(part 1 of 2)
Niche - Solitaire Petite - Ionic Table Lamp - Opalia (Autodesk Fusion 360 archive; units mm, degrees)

design "Marble Base - Ionic Table Lamp - Ketra Ready - 120V - Opalia Collection" references "Dart", "Orb 8.5In - Solitaire Petite", "Dart Petite", "Arca Petite", "Facet Petite", "Arca Tall", "Chinois", "Marble Base - Ionic Table Lamp - Ketra Ready - 120V", "Trove - TL", "Ketra - A20 Tunable Lamp"
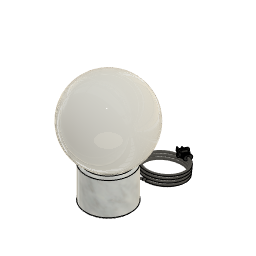
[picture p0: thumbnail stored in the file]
component_insert "Component Insert2"
component_insert "Component Insert3"
component_insert "Component Insert4"
component_insert "Component Insert5"
position "Position1"
component_insert "Component Insert6"
component_insert "Component Insert7"
component_insert "Component Insert8"
external_derived "ExternalDerived1" bodies "Orb-8.5"
derived_instance "DerivedInstance1"
position "Position2"
external_derived "ExternalDerived2" bodies "Dart Grand"
derived_instance "DerivedInstance2"
offset_faces "OffsetFaces1" distance -10.16
position "Position3"
external_derived "ExternalDerived3" bodies "Dart Petite"
derived_instance "DerivedInstance3"
offset_faces "OffsetFaces1" distance -10.16
position "Position4"
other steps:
derived_base_feature "Derived Base Feature1" bodies "Dart Grand"
derived_base_feature "Derived Base Feature1" bodies "Dart Petite"
derived_base_feature "Derived Base Feature1" bodies "Orb-8.5"
create_component "CreateComponent1"
create_component "CreateComponent2"
create_component "CreateComponent3"
named bodies: "Orb-8.5", "Dart Grand", "Dart Petite"

design "Dart Petite"
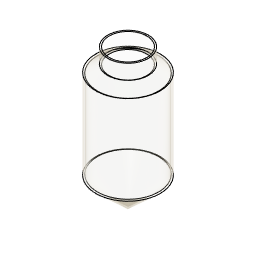
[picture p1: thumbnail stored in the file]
sketch "Sketch1" plane through (0, 0, 0) normal (0, 0, 1) x axis (1, 0, 0)
work_plane "WorkPlane1" AlongDistance 76.2
sketch "Sketch2" plane through (0, 0, 76.2) normal (0, 0, 1) x axis (1, 0, 0)
sketch "Sketch3" plane through (0, 0, 76.2) normal (0, 0, 1) x axis (1, 0, 0)
sketch "Sketch4" plane through (0, 0, 76.2) normal (0, 0, 1) x axis (1, 0, 0)
  circle C1 centre (0, 0) radius 82.55
  point P1 (0, 0)
  point P2 (0, 0)
  coincident P1 P2
  dimension "d2" diameter C1 = 165.1
loft "Loft1" sketch "Sketch4" bodies "Dart Petite"
extrude "Extrude1" add of existing geometry blind 228.6
work_plane "WorkPlane2" AlongDistance 19.05
sketch "Sketch5" plane through (0, 0, 323.85) normal (0, 0, 1) x axis (1, 0, 0)
  circle C1 centre (0, 0) radius 52.07
  point P1 (0, 0)
  point P2 (0, 0)
  coincident P1 P2
  dimension "d6" diameter C1 = 104.14
loft "Loft2" sketch "Sketch5"
extrude "Extrude2" add of existing geometry blind 38.1
shell "Shell3" innerThickness 3.81
component_from_bodies "Body->Comp"
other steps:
base_feature "Base Feature" bodies "Dart Petite"
create_component "CreateComponent1"
remove_body "RemoveBody1"
named bodies: "Dart Petite"

design "Marble Base - Ionic Table Lamp - Ketra Ready - 120V" references "Marble Base - Ionic Table Lamp - 120V"
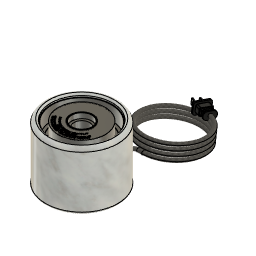
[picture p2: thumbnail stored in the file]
external_derived "ExternalDerived1" bodies "Coiled - SVT (Blk Fabric)", "Body1", "Marble Base", "Body2", "Silicone Gasket", "Plastic Insert"
derived_instance "DerivedInstance1"
derived_instance "DerivedInstance2"
derived_instance "DerivedInstance3"
derived_instance "DerivedInstance4"
derived_instance "DerivedInstance5"
derived_instance "DerivedInstance6"
derived_instance "DerivedInstance7"
derived_instance "DerivedInstance8"
derived_instance "DerivedInstance9"
derived_instance "DerivedInstance10"
derived_instance "DerivedInstance11"
derived_instance "DerivedInstance12"
offset_faces "OffsetFaces1" distance 3.81
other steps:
derived_base_feature "Derived Base Feature1" bodies "Rubber Grommet"
derived_base_feature "Derived Base Feature1" bodies "Neoprene Pad"
derived_base_feature "Derived Base Feature1" bodies "2-Pole Plug End"
derived_base_feature "Derived Base Feature1" bodies "Body1"
derived_base_feature "Derived Base Feature1" bodies "Body1", "Body2"
derived_base_feature "Derived Base Feature1" bodies "Body1"
derived_base_feature "Derived Base Feature1" bodies "Silicone Gasket"
derived_base_feature "Derived Base Feature1" bodies "Plastic Insert"
derived_base_feature "Derived Base Feature1" bodies "Body1"
derived_base_feature "Derived Base Feature1" bodies "Body1"
derived_base_feature "Derived Base Feature1" bodies "Coiled - SVT (Blk Fabric)"
derived_base_feature "Derived Base Feature1" bodies "Marble Base"
create_component "CreateComponent1"
create_component "CreateComponent2"
create_component "CreateComponent3"
create_component "CreateComponent4"
create_component "CreateComponent5"
create_component "CreateComponent6"
create_component "CreateComponent7"
create_component "CreateComponent8"
create_component "CreateComponent9"
create_component "CreateComponent10"
create_component "CreateComponent11"
create_component "CreateComponent12"
named bodies: "Coiled - SVT (Blk Fabric)", "Marble Base", "Body1", "Body2", "Plastic Insert", "Silicone Gasket", "Neoprene Pad", "2-Pole Plug End", "Rubber Grommet"

design "Arca Petite"
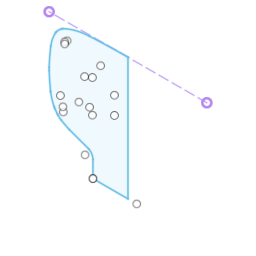
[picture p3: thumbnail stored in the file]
sketch "Sketch1" plane through (0, 0, 0) normal (0, 1, 0) x axis (1, 0, 0)
  line L1 (0, 101.6) -> (0, -101.6)
  line L2 (127, 0) -> (-127, 0)
  line L3 (63.5, 101.6) -> (-63.5, 101.6)
  perpendicular L1 L2
  parallel L2 L3
sketch "Sketch2" plane through (0, 0, 0) normal (0, 1, 0) x axis (1, 0, 0)
  line L1 (0, 101.6) -> (0, -101.6)
  line L2 (0, -76.2) -> (0, 101.6)
  line L3 (127, 0) -> (-127, 0)
  line L4 (114.3, 0) -> (-114.3, 0)
  line L5 (50.8, 101.6) -> (50.8, 63.5)
  line L6 (-50.8, 101.6) -> (50.8, 101.6)
  line L7 (-50.8, 63.5) -> (-50.8, 101.6)
  line L8 (63.5, 101.6) -> (-63.5, 101.6)
  line L9 (114.3, -76.2) -> (114.3, 63.5)
  line L10 (-114.3, -76.2) -> (114.3, -76.2)
  line L11 (-114.3, 63.5) -> (-114.3, -76.2)
  line L12 (-50.8, 63.5) -> (-114.3, 63.5)
  line L13 (114.3, 63.5) -> (50.8, 63.5)
  point P2 (0, 101.6)
  point P5 (0, 101.6)
  point P6 (0, -76.2)
  point P9 (-114.3, 0)
  point P10 (114.3, 0)
  point P11 (50.8, 101.6)
  point P19 (50.8, 63.5)
  coincident P2 P5
  coincident L1 P6
  coincident L3 P9
  coincident L3 P10
  vertical L5
  horizontal L6
  vertical L7
  coincident P11 L8
  horizontal L12
  vertical L9
  horizontal L10
  vertical L11
  coincident P19 L12
  collinear L12 L13
derived_base_feature "Derived Base Feature"
revolve "Revolve1" sketch "Sketch4" AlongAngle 360 bodies "Arca Petite"
shell "Shell1" innerThickness 3.81
component_from_bodies "Body->Comp"
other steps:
base_feature "Base Feature" bodies "Arca Petite"
create_component "CreateComponent1"
remove_body "RemoveBody1"
named bodies: "Arca Petite"

design "Neoprene Pad"
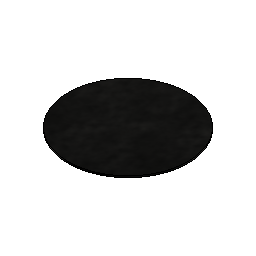
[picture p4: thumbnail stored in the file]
sketch "Sketch1" plane through (0, 0, 0) normal (0, 0, 1) x axis (1, 0, 0)
  circle C1 centre (0, 0) radius 57.15
  point P1 (0, 0)
  point P2 (0, 0)
  coincident P1 P2
extrude "Extrude1" new body sketch "Sketch1" along normal blind 1.5875 bodies "Neoprene Pad"
component_from_bodies "Body->Comp"
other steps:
base_feature "Base Feature" bodies "Neoprene Pad"
create_component "CreateComponent1"
remove_body "RemoveBody1"
named bodies: "Neoprene Pad"

design "T9 - Bulb"
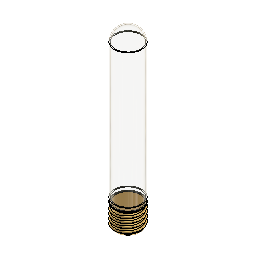
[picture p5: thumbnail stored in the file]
sketch "Sketch1" plane through (0, 0, 0) normal (0, 1, 0) x axis (1, 0, 0)
  line L1 (0, -166.37) -> (0, 0)
  line L2 (13.97, -13.97) -> (13.97, -152.4)
  line L3 (-13.97, -152.4) -> (-13.97, -13.97)
  line L4 (0, 0) -> (0, -166.37)
  line L5 (12.97, -13.97) -> (12.97, -152.4)
  line L6 (-12.97, -152.4) -> (-12.97, -13.97)
  line L7 (-12.3978, -10.16) -> (-13.4404, -10.16)
  line L8 (13.4404, -10.16) -> (12.3978, -10.16)
  arc A1 centre (0, -152.4) radius 13.97 clockwise from (13.97, -152.4) to (-13.97, -152.4)
  arc A2 centre (0, -152.4) radius 12.97 clockwise from (12.97, -152.4) to (-12.97, -152.4)
  arc A3 centre (0, -13.97) radius 13.97 clockwise from (13.4404, -10.16) to (13.97, -13.97)
  arc A4 centre (0, -13.97) radius 13.97 clockwise from (-13.97, -13.97) to (-13.4404, -10.16)
  arc A5 centre (0, -13.97) radius 12.97 clockwise from (12.3978, -10.16) to (12.97, -13.97)
  arc A6 centre (0, -13.97) radius 12.97 clockwise from (-12.97, -13.97) to (-12.3978, -10.16)
  point P1 (0, 0)
  point P2 (0, 0)
  point P3 (0, -166.37)
  point P10 (0, 0)
  point P17 (13.4404, -10.16)
  point P19 (12.3978, -10.16)
  point P4 (13.97, -152.4)
  point P5 (13.97, -13.97)
  coincident P1 P2
  vertical L1
  tangent L2 A3
  tangent L3 A3
  parallel L2 L3
  tangent L3 A1
  tangent L2 A1
  midpoint P3 A1
  coincident P1 P10
  perpendicular L1 L7
  coincident P17 L7
  concentric A3 A4
  coincident P10 A3
  concentric A1 A2
  tangent L5 A2
  tangent L5 A5
  tangent L6 A5
  tangent L6 A2
  coincident P19 L7
  concentric A5 A6
  collinear L7 L8
  dimension "d6" distance L2 L3 = 27.94
  dimension "d7" distance P4 P5 = 138.43
revolve "Revolve1" sketch "Sketch1" AlongAngle 360 bodies "T9"
derived_base_feature "Derived Base Feature" bodies "E26 Base"
align "Align1"
move "Move1"
component_from_bodies "Body->Comp1"
component_from_bodies "Body->Comp2"
copy_paste "CutPaste1"
copy_paste "CutPaste2"
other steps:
base_feature "Base Feature1" bodies "T9"
base_feature "Base Feature1" bodies "E26 Base"
create_component "CreateComponent1"
create_component "CreateComponent2"
remove_body "RemoveBody1"
create_component "CreateComponent3"
remove_body "RemoveBody2"
remove_instance "RemoveInstance1"
remove_instance "RemoveInstance2"
named bodies: "T9", "E26 Base"

design "Facet Petite"
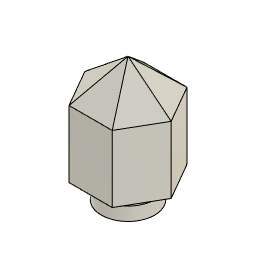
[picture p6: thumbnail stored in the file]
sketch "Sketch7" plane through (0, 0, 0) normal (1, 0, 0) x axis (0, 1, 0)
sketch "Sketch8" plane through (0, 0, 0) normal (0, 0, 1) x axis (1, 0, 0)
  circle C1 centre (0, 0) radius 50.8
  point P1 (0, 0)
  point P2 (0, 0)
  coincident P1 P2
  dimension "d17" diameter C1 = 101.6
extrude "Extrude5" new body sketch "Sketch8" along normal blind 25.4 and against normal blind 25.4
work_plane "WorkPlane1" AlongDistance 17.78
sketch "Sketch10" plane through (0, 0, 25.4) normal (0, 0, 1) x axis (-1, 0, 0)
  circle C1 centre (0, 0) radius 50.8
sketch "Sketch12" plane through (0, 0, 43.18) normal (0, 0, 1) x axis (1, 0, 0)
  line L1 (-82.1223, 0) -> (-41.0612, 71.12)
  line L2 (-41.0612, -71.12) -> (-82.1223, 0)
  line L3 (41.0612, -71.12) -> (-41.0612, -71.12)
  line L4 (82.1223, 0) -> (41.0612, -71.12)
  line L5 (41.0612, 71.12) -> (82.1223, 0)
  line L6 (-41.0612, 71.12) -> (41.0612, 71.12)
  point P1 (0, 0)
  point P8 (0, 0)
  coincident P1 P8
  dimension "d22" distance P8 L6 = 71.12
sketch "Sketch15" plane through (0, 0, 0) normal (0, 1, 0) x axis (1, 0, 0)
  line L1 (53.7365, -21.6801) -> (82.1223, -43.18)
  line L2 (-50.8, -25.4) -> (-82.1223, -43.18)
  point P2 (82.1223, -43.18)
  point P3 (82.1223, -43.18)
  point P5 (-82.1223, -43.18)
  point P7 (-82.1223, -43.18)
  point P6 (-50.8, -25.4)
  point P8 (-50.8, -25.4)
  coincident P2 P3
  coincident P5 P7
  coincident P6 P8
sketch "Sketch17" plane through (0, 0, 25.4) normal (0, 0, 1) x axis (-1, 0, 0)
  line L1 (51.3255, 0) -> (0, 0)
  line L2 (73.3235, 0) -> (0, 0)
  line L3 (-41.0612, -71.12) -> (-25.4, -43.9941)
  line L4 (-36.6617, -63.5) -> (-25.4, -43.9941)
  line L5 (78.4305, 0) -> (0, 0)
  line L6 (41.0612, -71.12) -> (25.4, -43.9941)
  line L7 (25.4, 43.9941) -> (41.0612, 71.12)
  line L8 (73.3235, 0) -> (0, 0)
  line L9 (-25.4, 43.9941) -> (-41.0612, 71.12)
  line L10 (0, 0) -> (0, 0)
  circle C1 centre (0, 0) radius 50.8
  point P1 (0, 0)
  point P4 (0, 0)
  point P2 (-41.0612, -71.12)
  point P6 (-41.0612, -71.12)
  point P3 (0, 0)
  point P7 (0, 0)
  point P9 (-25.4, -43.9941)
  point P12 (41.0612, -71.12)
  point P13 (41.0612, -71.12)
  point P15 (25.4, -43.9941)
  point P16 (41.0612, 71.12)
  point P17 (41.0612, 71.12)
  point P18 (25.4, 43.9941)
  point P19 (-41.0612, 71.12)
  point P20 (-41.0612, 71.12)
  point P21 (0, 0)
  point P23 (-25.4, 43.9941)
  point P25 (0, 0)
  point P24 (0, 0)
  point P26 (0, 0)
  horizontal L1
  coincident P1 P4
  coincident P2 P6
  horizontal L2
  coincident P3 P7
  coincident C1 P9
  coincident P12 P13
  horizontal L5
  coincident C1 P15
  coincident P16 P17
  coincident C1 P18
  coincident P19 P20
  horizontal L8
  coincident P1 P21
  coincident C1 P23
  coincident P1 P25
  coincident P24 P26
extrude "Extrude6" new body sketch "Sketch12" along normal blind 127
work_plane "WorkPlane2" AlongDistance 66.04
sketch "Sketch18" plane through (0, 0, 236.22) normal (0, 0, 1) x axis (1, 0, 0)
  line L1 (41.0612, -71.12) -> (0, 0)
  line L2 (82.1223, 0) -> (0, 0)
  line L3 (41.0612, 71.12) -> (0, 0)
  line L4 (-41.0612, 71.12) -> (0, 0)
  line L5 (-82.1223, 0) -> (0, 0)
  line L6 (-41.0612, -71.12) -> (0, 0)
  point P1 (0, 0)
  point P3 (0, 0)
  point P2 (41.0612, -71.12)
  point P4 (41.0612, -71.12)
  point P6 (0, 0)
  point P5 (82.1223, 0)
  point P7 (82.1223, 0)
  point P9 (0, 0)
  point P8 (41.0612, 71.12)
  point P10 (41.0612, 71.12)
  point P12 (0, 0)
  point P11 (-41.0612, 71.12)
  point P13 (-41.0612, 71.12)
  point P15 (0, 0)
  point P14 (-82.1223, 0)
  point P16 (-82.1223, 0)
  point P18 (0, 0)
  point P17 (-41.0612, -71.12)
  point P19 (-41.0612, -71.12)
  coincident P1 P3
  coincident P2 P4
  coincident P1 P6
  coincident P5 P7
  coincident P1 P9
  coincident P8 P10
  coincident P1 P12
  coincident P11 P13
  coincident P1 P15
  coincident P14 P16
  coincident P1 P18
  coincident P17 P19
loft "Loft1"
loft "Loft2" sketch "Sketch17"
component_from_bodies "Body->Comp"
extrude "Extrude1" cut of existing geometry blind -25.4
shell "Shell2" innerThickness 3.81
fillet "Fillet1" radius 7.62
fillet "Fillet2" radius 6.35
fillet "Fillet3" radius 6.35
fillet "Fillet4" radius 6.35
fillet "Fillet5" radius 6.35
fillet "Fillet6" radius 6.35
fillet "Fillet7" radius 3.81
fillet "Fillet8" radius 6.35
fillet "Fillet9" radius 6.35
fillet "Fillet10" radius 6.35
fillet "Fillet11" radius 6.35
fillet "Fillet12" radius 6.35
fillet "Fillet13" radius 2.286
shell "Shell1" innerThickness 2.54
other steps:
base_feature "Base Feature"
create_component "CreateComponent3"
remove_body "RemoveBody2"

design "Marble Base - Ionic Table Lamp - 120V" references "Dart", "Rubber Grommet", "Marble Base - Plastic Insert", "Chinois", "2-Pole Plug End", "Neoprene Pad", "Marble Base - Silicone Gasket", "Trove - TL", "Dart Petite", "Balon v2", "T9 - Bulb", "Orb 8.5In - Solitaire Petite", "T9-5In", "T8 LED 11", "Arca Tall", "Facet Petite"
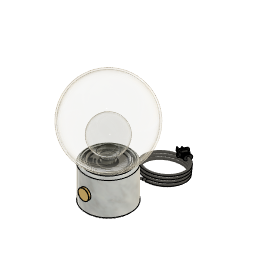
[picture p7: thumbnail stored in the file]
sketch "Sketch1" plane through (0, 0, 0) normal (0, 0, 1) x axis (1, 0, 0)
  circle C1 centre (0, 0) radius 63.5
  point P1 (0, 0)
  point P2 (0, 0)
  coincident P1 P2
extrude "Extrude1" new body sketch "Sketch1" along normal blind 101.6 bodies "Marble Base"
sketch "Sketch2" plane through (0, 0, 101.6) normal (0, 0, 1) x axis (-1, 0, 0)
  circle C1 centre (0, 0) radius 63.5
  circle C2 centre (0, 0) radius 53.975
  concentric C1 C2
  dimension "d3" diameter C2 = 107.95
extrude "Extrude2" cut sketch "Sketch2" profile of C2 against normal blind 34.925
sketch "Sketch3" plane through (0, 0, 66.675) normal (0, 0, 1) x axis (-1, 0, 0)
  circle C1 centre (0, 0) radius 53.975
  circle C2 centre (0, 0) radius 49.276
  point P1 (0, 0)
  point P3 (0, 0)
  coincident P1 P3
  dimension "d6" diameter C2 = 98.552
extrude "Extrude3" cut sketch "Sketch3" profile of C2 against normal blind 45.72
sketch "Sketch4" plane through (0, 0, 0) normal (0, 1, 0) x axis (1, 0, 0)
  circle C1 centre (0, -50.8) radius 3.81
  dimension "d9" diameter C1 = 7.62
extrude "Extrude4" cut sketch "Sketch4" against normal blind 127
sketch "Sketch5" plane through (0, 0, 0) normal (0, 1, 0) x axis (1, 0, 0)
  line L1 (0, -25.4) -> (0, 0)
  line L2 (0, -30.48) -> (0, -25.4)
  circle C1 centre (0, -30.48) radius 5.08
  point P1 (0, 0)
  point P2 (0, 0)
  point P4 (0, -30.48)
  point P5 (0, -30.48)
  coincident P1 P2
  vertical L1
  parallel L1 L2
  coincident P4 P5
  dimension "d12" diameter C1 = 10.16
extrude "Extrude5" cut sketch "Sketch5" profile of C1 along normal blind 114.3
fillet "Fillet1" radius 6.35 3.175 4.064
derived_base_feature "Derived Base Feature1" bodies "Rotary Switch"
derived_base_feature "Derived Base Feature1" bodies "Coiled - SVT (Blk Fabric)"
derived_base_feature "Derived Base Feature1" bodies "Glass Globe"
derived_base_feature "Derived Base Feature1" bodies "Metal Housing"
derived_base_feature "Derived Base Feature1" bodies "Metal Socket Cover"
derived_base_feature "Derived Base Feature1" bodies "Porcelain Socket"
derived_base_feature "Derived Base Feature1" bodies "Brass Dial - Dimmer Knob"
component_from_bodies "Body->Comp1"
offset_faces "OffsetFaces1" distance 12.7
offset_faces "OffsetFaces2" distance -12.7
derived_base_feature "Derived Base Feature1" bodies "Solitaire Petite"
move "Move1"
offset_faces "OffsetFaces1" distance 20.32
move "Move2"
extrude "Extrude6" add of existing geometry blind 25.4
offset_faces "OffsetFaces2" distance -3.81
fillet "Fillet2" radius 2.54
move "Move3"
derived_base_feature "Derived Base Feature2" bodies "Facet Petite"
move "Move4"
offset_faces "OffsetFaces1" distance 2.54
move "Move1"
derived_base_feature "Derived Base Feature1" bodies "Body1"
derived_base_feature "Derived Base Feature1" bodies "Body1"
derived_base_feature "Derived Base Feature1" bodies "Body1"
derived_base_feature "Derived Base Feature1" bodies "Body1"
derived_base_feature "Derived Base Feature1" bodies "Body1"
derived_base_feature "Derived Base Feature1" bodies "Body1", "Body2"
derived_base_feature "Derived Base Feature1" bodies "Body1"
position "Position1"
external_derived "ExternalDerived5" bodies "Plastic Insert"
derived_instance "DerivedInstance15"
offset_faces "OffsetFaces1" distance 3.81
offset_faces "OffsetFaces2" distance -1.0414
move "Move6"
external_derived "ExternalDerived6" sketch "Sketch3" bodies "Silicone Gasket"
derived_instance "DerivedInstance16"
offset_faces "OffsetFaces3" distance -10.795
move "Move1"
move_face "MoveFace1"
position "Position2"
position "Position3"
position "Position4"
position "Position5"
move "Move2"
position "Position6"
offset_faces "OffsetFaces2" distance -7.62
chamfer "Chamfer1" distance 0.381
remove_instance "RemoveInstance1"
remove_instance "RemoveInstance2"
remove_instance "RemoveInstance3"
remove_instance "RemoveInstance4"
move "Move1"
derived_base_feature "Derived Base Feature5" bodies "Oculo Petite"
align "Align1"
external_derived "ExternalDerived8"
derived_base_feature "Derived Base Feature7" bodies "Balon v2"
derived_base_feature "Derived Base Feature8" bodies "Balon v3"
align "Align3"
align "Align4"
external_derived "ExternalDerived10"
component_insert "Component Insert1"
position "Position7"
position "Position8"
derived_base_feature "Derived Base Feature11" bodies "Trove - TL"
move "Move10"
move "Move11"
remove_instance "RemoveInstance5"
split "Split1" bodies "Trove - TL (1)"
remove_body "RemoveBody2"
remove_body "RemoveBody3"
external_derived "ExternalDerived13" bodies "Trove - TL"
derived_instance "DerivedInstance20"
remove_body "RemoveBody4"
remove_body "RemoveBody5"
component_insert "Component Insert2"
component_insert "Component Insert3"
component_from_bodies "Body->Comp2"
remove_body "RemoveBody7"
move "Move12"
move "Move13"
sketch "Sketch6" plane through (0, 0, 97.917) normal (0, 0, 1) x axis (-1, 0, 0)
  circle C1 centre (0, 0) radius 41.275
  circle C2 centre (0, 0) radius 19.685
  arc A1 centre (0, 0) radius 29.3982 clockwise from (-27.6283, 10.0466) to (27.6283, 10.0466)
  arc A2 centre (0, 0) radius 26.2232 clockwise from (-24.6444, 8.9616) to (24.6444, 8.9616)
  arc A3 centre (0, 0) radius 32.5732 clockwise from (-30.6121, 11.1317) to (30.6121, 11.1317)
  arc A4 centre (0, 0) radius 35.7482 clockwise from (-33.596, 12.2167) to (33.596, 12.2167)
  point P1 (0, 0)
  point P3 (0, 0)
  coincident P1 P3
  dimension "d37" = -3.175
  dimension "d38" = 3.175
  dimension "d39" = 6.35
  dimension "d40" Text1-Height = 2.54
  dimension "d41" Text2-Height = 2.54
  dimension "d42" Text3-Height = 2.54
  dimension "d43" Text4-Height = 2.54
extrude "Extrude1" cut sketch "Sketch6" against normal blind 0.254
external_derived "ExternalDerived14" bodies "Rubber Grommet"
derived_instance "DerivedInstance19"
external_derived "ExternalDerived15" bodies "2-Pole Plug End"
derived_instance "DerivedInstance18"
external_derived "ExternalDerived16" bodies "Neoprene Pad"
derived_instance "DerivedInstance17"
position "Position9"
position "Position10"
position "Position11"
position "Position12"
external_derived "ExternalDerived17" bodies "Chinois"
derived_instance "DerivedInstance21"
position "Position13"
move "Move3"
remove_body "RemoveBody8"
component_insert "Component Insert4"
offset_faces "OffsetFaces3" distance 50.8
component_insert "Component Insert5"
position "Position14"
external_derived "ExternalDerived18" bodies "Dart Grand"
derived_instance "DerivedInstance22"
offset_faces "OffsetFaces1" distance -10.16
position "Position15"
external_derived "ExternalDerived19" bodies "Dart Petite"
derived_instance "DerivedInstance23"
offset_faces "OffsetFaces1" distance -10.16
position "Position16"
component_insert "Component Insert6"
position "Position17"
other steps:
derived_base_feature "Derived Base Feature1" bodies "Trove - TL"
derived_base_feature "Derived Base Feature1" bodies "Chinois"
derived_base_feature "Derived Base Feature1" bodies "Dart Grand"
derived_base_feature "Derived Base Feature1" bodies "Dart Petite"
derived_base_feature "Derived Base Feature1" bodies "Rubber Grommet"
derived_base_feature "Derived Base Feature1" bodies "Neoprene Pad"
derived_base_feature "Derived Base Feature1" bodies "2-Pole Plug End"
move "Move1"
derived_base_feature "Derived Base Feature1" bodies "Plastic Insert"
derived_base_feature "Derived Base Feature1" bodies "Silicone Gasket"
base_feature "Base Feature1" bodies "Oculo Petite", "Arca Petite"
base_feature "Base Feature1" bodies "Marble Base"
move "Move8"
derived_base_feature "Derived Base Feature"
create_component "CreateComponent1"
create_component "CreateComponent2"
create_component "CreateComponent3"
create_component "CreateComponent4"
create_component "CreateComponent5"
create_component "CreateComponent6"
create_component "CreateComponent7"
create_component "CreateComponent8"
remove_body "RemoveBody1"
create_component "CreateComponent9"
create_component "CreateComponent10"
create_component "CreateComponent11"
create_component "CreateComponent12"
create_component "CreateComponent13"
create_component "CreateComponent14"
create_component "CreateComponent15"
create_component "CreateComponent16"
create_component "CreateComponent17"
create_component "CreateComponent18"
remove_body "RemoveBody6"
create_component "CreateComponent19"
create_component "CreateComponent20"
create_component "CreateComponent21"
create_component "CreateComponent22"
create_component "CreateComponent23"
create_component "CreateComponent24"
create_component "CreateComponent25"
named bodies: "Marble Base", "Rotary Switch", "Coiled - SVT (Blk Fabric)", "Glass Globe", "Metal Housing", "Metal Socket Cover", "Porcelain Socket", "Brass Dial - Dimmer Knob", "Solitaire Petite", "Facet Petite", "Body1", "Body2", "Plastic Insert", "Silicone Gasket", "Oculo Petite", "Balon v2", "Balon v3", "Trove - TL", "Trove - TL (1)", "Arca Petite", "Neoprene Pad", "2-Pole Plug End", "Rubber Grommet", "Chinois", "Dart Grand", "Dart Petite"

design "Marble Base - Silicone Gasket"
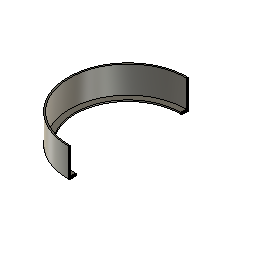
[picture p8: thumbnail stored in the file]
sketch "Sketch1" plane through (0, 0, 0) normal (0, 0, 1) x axis (1, 0, 0)
  circle C1 centre (0, 0) radius 53.34
  point P1 (0, 0)
  point P2 (0, 0)
  coincident P1 P2
extrude "Extrude1" new body sketch "Sketch1" along normal blind 25.4 bodies "Silicone Gasket"
shell "Shell1" innerThickness 1.27
sketch "Sketch2" plane through (0, 0, 1.27) normal (0, 0, 1) x axis (-1, 0, 0)
  circle C1 centre (0, 0) radius 52.07
  circle C2 centre (0, 0) radius 46.99
  concentric C1 C2
extrude "Extrude2" cut sketch "Sketch2" profile of C2 against normal blind 12.7
component_from_bodies "Body->Comp"
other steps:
base_feature "Base Feature" bodies "Silicone Gasket"
create_component "CreateComponent1"
remove_body "RemoveBody1"
named bodies: "Silicone Gasket"

design "Balon v2"
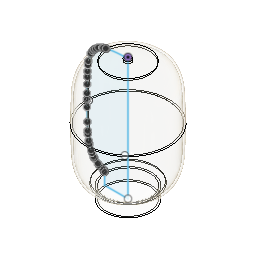
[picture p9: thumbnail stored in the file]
derived_base_feature "Derived Base Feature" bodies "Balon"
work_plane "WorkPlane1" AlongDistance 0
sketch "Sketch1" plane through (0, 0, 0) normal (0, 1, 0) x axis (1, 0, 0)
  line L1 (0, 317.5) -> (0, 2.9083)
  curve K1 (-82.9821, 124.2212) -> (-50.8, 237.8015)
  curve K2 (-51.0925, 237.681) -> (-50.8, 237.8015)
  curve K3 (-51.3855, 237.5558) -> (-51.0925, 237.681)
  curve K4 (-54.7608, 236.0513) -> (-51.3855, 237.5558)
  curve K5 (-57.9615, 234.05) -> (-54.7608, 236.0513)
  curve K6 (-67.2727, 226.749) -> (-57.9615, 234.05)
  curve K7 (-69.0552, 224.2615) -> (-67.2727, 226.749)
  curve K8 (-72.1872, 218.7832) -> (-69.0552, 224.2615)
  curve K9 (-74.1213, 215.1556) -> (-72.1872, 218.7832)
  curve K10 (-78.3031, 204.3965) -> (-74.1213, 215.1556)
  curve K11 (-79.7275, 197.3397) -> (-78.3031, 204.3965)
  curve K12 (-81.3333, 185.4664) -> (-79.7275, 197.3397)
  curve K13 (-81.6254, 178.4008) -> (-81.3333, 185.4664)
  curve K14 (-82.49, 152.2133) -> (-81.6254, 178.4008)
  curve K15 (-82.9821, 136.067) -> (-82.49, 152.2133)
  curve K16 (-82.9821, 124.2212) -> (-82.9821, 136.067)
  curve K17 (50.8, 237.7999) -> (82.9821, 124.2212)
  curve K18 (82.9821, 140.3031) -> (82.9821, 124.2212)
  curve K19 (81.9353, 169.4257) -> (82.9821, 140.3031)
  curve K20 (81.3621, 183.6489) -> (81.9353, 169.4257)
  curve K21 (80.9478, 189.8724) -> (81.3621, 183.6489)
  curve K22 (77.8147, 206.9858) -> (80.9478, 189.8724)
  curve K23 (74.9652, 213.2153) -> (77.8147, 206.9858)
  curve K24 (69.4688, 224.1531) -> (74.9652, 213.2153)
  curve K25 (67.2512, 226.458) -> (69.4688, 224.1531)
  curve K26 (61.5696, 231.3138) -> (67.2512, 226.458)
  curve K27 (57.377, 234.6711) -> (61.5696, 231.3138)
  curve K28 (52.0556, 237.2628) -> (57.377, 234.6711)
  curve K29 (51.4313, 237.5413) -> (52.0556, 237.2628)
  curve K30 (50.8, 237.7999) -> (51.4313, 237.5413)
  line L2 (-50.8, 317.5) -> (-50.8, 237.8015)
  line L3 (50.8, 317.5) -> (50.8, 237.7999)
  line L4 (-19.0713, 6.7501) -> (-19.0713, 6.7501)
  curve K31 (82.9821, 124.1958) -> (40.1509, 7.3012)
  curve K32 (41.8198, 7.6176) -> (40.1509, 7.3012)
  curve K33 (43.2113, 8.0663) -> (41.8198, 7.6176)
  curve K34 (47.0139, 9.2854) -> (43.2113, 8.0663)
  curve K35 (47.3314, 9.3805) -> (47.0139, 9.2854)
  curve K36 (50.1192, 10.3272) -> (47.3314, 9.3805)
  curve K37 (51.833, 11.0085) -> (50.1192, 10.3272)
  curve K38 (57.8313, 14.1895) -> (51.833, 11.0085)
  curve K39 (61.4491, 17.0488) -> (57.8313, 14.1895)
  curve K40 (66.8203, 21.5867) -> (61.4491, 17.0488)
  curve K41 (68.5372, 23.5528) -> (66.8203, 21.5867)
  curve K42 (71.2201, 27.8971) -> (68.5372, 23.5528)
  curve K43 (74.7424, 33.8984) -> (71.2201, 27.8971)
  curve K44 (78.2342, 44.8406) -> (74.7424, 33.8984)
  curve K45 (79.6792, 50.3463) -> (78.2342, 44.8406)
  curve K46 (81.3558, 63.5576) -> (79.6792, 50.3463)
  curve K47 (81.6386, 70.4415) -> (81.3558, 63.5576)
  curve K48 (82.4897, 96.2198) -> (81.6386, 70.4415)
  curve K49 (82.9814, 112.3523) -> (82.4897, 96.2198)
  curve K50 (82.9821, 124.1958) -> (82.9814, 112.3523)
  curve K51 (-40.1501, 7.301) -> (-82.9821, 124.1958)
  curve K52 (-82.9813, 110.5256) -> (-82.9821, 124.1958)
  curve K53 (-82.2545, 88.8594) -> (-82.9813, 110.5256)
  curve K54 (-81.6277, 70.519) -> (-82.2545, 88.8594)
  curve K55 (-81.3572, 64.3441) -> (-81.6277, 70.519)
  curve K56 (-79.4149, 46.8924) -> (-81.3572, 64.3441)
  curve K57 (-76.5204, 38.9768) -> (-79.4149, 46.8924)
  curve K58 (-73.5142, 32.2947) -> (-76.5204, 38.9768)
  curve K59 (-72.5556, 30.3818) -> (-73.5142, 32.2947)
  curve K60 (-69.7914, 25.3691) -> (-72.5556, 30.3818)
  curve K61 (-68.3824, 23.4028) -> (-69.7914, 25.3691)
  curve K62 (-64.5419, 19.5456) -> (-68.3824, 23.4028)
  curve K63 (-62.3002, 17.7646) -> (-64.5419, 19.5456)
  curve K64 (-53.6583, 11.1976) -> (-62.3002, 17.7646)
  curve K65 (-49.6968, 10.1396) -> (-53.6583, 11.1976)
  curve K66 (-43.4141, 8.1331) -> (-49.6968, 10.1396)
  curve K67 (-41.9704, 7.6516) -> (-43.4141, 8.1331)
  curve K68 (-40.1963, 7.3098) -> (-41.9704, 7.6516)
  curve K69 (-40.1732, 7.3054) -> (-40.1963, 7.3098)
  curve K70 (-40.1501, 7.301) -> (-40.1732, 7.3054)
  line L5 (-82.9821, 124.1958) -> (-82.9821, 124.2212)
  line L6 (82.9821, 124.2212) -> (82.9821, 124.1958)
  line L7 (0, 317.5) -> (-50.8, 317.5)
  line L8 (7.2015, 3.048) -> (0, 3.048)
  line L9 (0, 3.048) -> (-7.2015, 3.048)
  arc A1 centre (0, 188.595) radius 185.6867 clockwise from (-7.2015, 3.048) to (-40.1502, 7.301)
  arc A2 centre (0, 188.595) radius 185.6867 clockwise from (40.151, 7.3012) to (7.2015, 3.048)
  point P38 (-40.1502, 7.301)
  point P43 (40.1509, 7.3012)
  point P62 (-40.1501, 7.301)
  point P81 (40.151, 7.3012)
  point P84 (0, 3.048)
  vertical L1
  horizontal L4
  coincident P38 K51
  symmetric L1 A1 A2
  coincident A2 P43
  coincident A1 P62
  coincident K31 P81
  perpendicular L2 L7
  horizontal L8
  coincident L1 P84
  horizontal L9
revolve "Revolve1" sketch "Sketch1" AlongAngle 360
shell "Shell1" innerThickness 3.81
fillet "Fillet1" radius 6.35
offset_faces "OffsetFaces1" distance -50.8
move "Move1"
move "Move2"
component_from_bodies "Body->Comp1"
component_from_bodies "Body->Comp2"
sketch "Sketch2" plane through (0, 0, 0) normal (0, 1, 0) x axis (1, 0, 0)
  line L1 (-85.5221, 124.2212) -> (-85.5221, 124.1961)
  curve K1 (-58.9057, 236.4383) -> (-50.8, 241.7989)
  curve K2 (-50.8, 241.554) -> (-50.8, 241.7989)
  curve K3 (-50.904, 240.933) -> (-50.8, 241.554)
  curve K4 (-51.2936, 240.2837) -> (-50.904, 240.933)
  curve K5 (-51.734, 239.7561) -> (-51.2936, 240.2837)
  curve K6 (-53.328, 238.5038) -> (-51.734, 239.7561)
  curve K7 (-54.0892, 238.1997) -> (-53.328, 238.5038)
  curve K8 (-58.9057, 236.4383) -> (-54.0892, 238.1997)
  curve K9 (-89.3309, 124.2212) -> (-58.9057, 236.4383)
  curve K10 (-62.6336, 234.9735) -> (-58.9057, 236.4383)
  curve K11 (-65.581, 233.1032) -> (-62.6336, 234.9735)
  curve K12 (-73.0224, 227.0019) -> (-65.581, 233.1032)
  curve K13 (-74.8981, 224.836) -> (-73.0224, 227.0019)
  curve K14 (-78.1104, 219.6097) -> (-74.8981, 224.836)
  curve K15 (-80.2663, 215.561) -> (-78.1104, 219.6097)
  curve K16 (-84.0943, 205.8277) -> (-80.2663, 215.561)
  curve K17 (-85.4655, 200.1154) -> (-84.0943, 205.8277)
  curve K18 (-87.4092, 188.5789) -> (-85.4655, 200.1154)
  curve K19 (-87.7349, 182.3889) -> (-87.4092, 188.5789)
  curve K20 (-88.4233, 165.9645) -> (-87.7349, 182.3889)
  curve K21 (-89.328, 138.6964) -> (-88.4233, 165.9645)
  curve K22 (-89.3309, 124.2212) -> (-89.328, 138.6964)
  line L2 (-89.3309, 124.1958) -> (-89.3309, 124.2212)
  curve K23 (-46.5001, 7.301) -> (-89.3309, 124.1958)
  curve K24 (-89.3314, 112.4293) -> (-89.3309, 124.1958)
  curve K25 (-88.8181, 95.3068) -> (-89.3314, 112.4293)
  curve K26 (-88.346, 81.2892) -> (-88.8181, 95.3068)
  curve K27 (-88.0298, 70.4902) -> (-88.346, 81.2892)
  curve K28 (-87.1514, 58.328) -> (-88.0298, 70.4902)
  curve K29 (-86.3326, 50.6119) -> (-87.1514, 58.328)
  curve K30 (-81.0932, 33.6688) -> (-86.3326, 50.6119)
  curve K31 (-77.3163, 27.4309) -> (-81.0932, 33.6688)
  curve K32 (-74.8955, 23.6666) -> (-77.3163, 27.4309)
  curve K33 (-73.5108, 22.0741) -> (-74.8955, 23.6666)
  curve K34 (-70.2346, 19.0457) -> (-73.5108, 22.0741)
  curve K35 (-64.8094, 14.3548) -> (-70.2346, 19.0457)
  curve K36 (-56.6696, 10.3041) -> (-64.8094, 14.3548)
  curve K37 (-54.0053, 9.483) -> (-56.6696, 10.3041)
  curve K38 (-49.1487, 7.9411) -> (-54.0053, 9.483)
  curve K39 (-48.3482, 7.6526) -> (-49.1487, 7.9411)
  curve K40 (-46.5001, 7.301) -> (-48.3482, 7.6526)
  line L3 (0, 266.7) -> (0, 0)
  line L4 (0, 3.048) -> (-7.7894, 3.048)
  line L5 (-50.8, 266.7) -> (-50.8, 241.7989)
  line L6 (0, 266.7) -> (-50.8, 266.7)
  arc A1 centre (-6.9779, 188.7329) radius 185.6867 clockwise from (-7.7894, 3.048) to (-46.5001, 7.301)
  point P1 (0, 0)
  point P44 (0, 0)
  point P46 (0, 3.048)
  point P5 (-50.8, 241.554)
  point P49 (0, 266.7)
  coincident P1 P44
  coincident L3 P46
  coincident P5 L5
  coincident L3 P49
revolve "Revolve2" sketch "Sketch2" AlongAngle 360 bodies "Balon v3"
shell "Shell2" innerThickness 3.81
component_from_bodies "Body->Comp3"
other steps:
base_feature "Base Feature1" bodies "Balon"
base_feature "Base Feature1" bodies "Balon v3"
base_feature "Base Feature1" bodies "Balon v2"
create_component "CreateComponent1"
remove_body "RemoveBody1"
create_component "CreateComponent2"
remove_body "RemoveBody2"
create_component "CreateComponent3"
remove_body "RemoveBody3"
named bodies: "Balon", "Balon v2", "Balon v3"

design "Arca Tall"
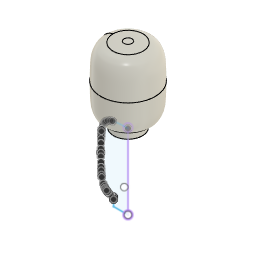
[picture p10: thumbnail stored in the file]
derived_base_feature "Derived Base Feature" bodies "Balon"
work_plane "WorkPlane1" AlongDistance 0
sketch "Sketch1" plane through (0, 0, 0) normal (0, 1, 0) x axis (1, 0, 0)
  line L1 (0, 317.5) -> (0, 2.9083)
  curve K1 (-82.9821, 124.2212) -> (-50.8, 237.8015)
  curve K2 (-51.0925, 237.681) -> (-50.8, 237.8015)
  curve K3 (-51.3855, 237.5558) -> (-51.0925, 237.681)
  curve K4 (-54.7608, 236.0513) -> (-51.3855, 237.5558)
  curve K5 (-57.9615, 234.05) -> (-54.7608, 236.0513)
  curve K6 (-67.2727, 226.749) -> (-57.9615, 234.05)
  curve K7 (-69.0552, 224.2615) -> (-67.2727, 226.749)
  curve K8 (-72.1872, 218.7832) -> (-69.0552, 224.2615)
  curve K9 (-74.1213, 215.1556) -> (-72.1872, 218.7832)
  curve K10 (-78.3031, 204.3965) -> (-74.1213, 215.1556)
  curve K11 (-79.7275, 197.3397) -> (-78.3031, 204.3965)
  curve K12 (-81.3333, 185.4664) -> (-79.7275, 197.3397)
  curve K13 (-81.6254, 178.4008) -> (-81.3333, 185.4664)
  curve K14 (-82.49, 152.2133) -> (-81.6254, 178.4008)
  curve K15 (-82.9821, 136.067) -> (-82.49, 152.2133)
  curve K16 (-82.9821, 124.2212) -> (-82.9821, 136.067)
  curve K17 (50.8, 237.7999) -> (82.9821, 124.2212)
  curve K18 (82.9821, 140.3031) -> (82.9821, 124.2212)
  curve K19 (81.9353, 169.4257) -> (82.9821, 140.3031)
  curve K20 (81.3621, 183.6489) -> (81.9353, 169.4257)
  curve K21 (80.9478, 189.8724) -> (81.3621, 183.6489)
  curve K22 (77.8147, 206.9858) -> (80.9478, 189.8724)
  curve K23 (74.9652, 213.2153) -> (77.8147, 206.9858)
  curve K24 (69.4688, 224.1531) -> (74.9652, 213.2153)
  curve K25 (67.2512, 226.458) -> (69.4688, 224.1531)
  curve K26 (61.5696, 231.3138) -> (67.2512, 226.458)
  curve K27 (57.377, 234.6711) -> (61.5696, 231.3138)
  curve K28 (52.0556, 237.2628) -> (57.377, 234.6711)
  curve K29 (51.4313, 237.5413) -> (52.0556, 237.2628)
  curve K30 (50.8, 237.7999) -> (51.4313, 237.5413)
  line L2 (-50.8, 317.5) -> (-50.8, 237.8015)
  line L3 (50.8, 317.5) -> (50.8, 237.7999)
  line L4 (-19.0713, 6.7501) -> (-19.0713, 6.7501)
  curve K31 (82.9821, 124.1958) -> (40.1509, 7.3012)
  curve K32 (41.8198, 7.6176) -> (40.1509, 7.3012)
  curve K33 (43.2113, 8.0663) -> (41.8198, 7.6176)
  curve K34 (47.0139, 9.2854) -> (43.2113, 8.0663)
  curve K35 (47.3314, 9.3805) -> (47.0139, 9.2854)
  curve K36 (50.1192, 10.3272) -> (47.3314, 9.3805)
  curve K37 (51.833, 11.0085) -> (50.1192, 10.3272)
  curve K38 (57.8313, 14.1895) -> (51.833, 11.0085)
  curve K39 (61.4491, 17.0488) -> (57.8313, 14.1895)
  curve K40 (66.8203, 21.5867) -> (61.4491, 17.0488)
  curve K41 (68.5372, 23.5528) -> (66.8203, 21.5867)
  curve K42 (71.2201, 27.8971) -> (68.5372, 23.5528)
  curve K43 (74.7424, 33.8984) -> (71.2201, 27.8971)
  curve K44 (78.2342, 44.8406) -> (74.7424, 33.8984)
  curve K45 (79.6792, 50.3463) -> (78.2342, 44.8406)
  curve K46 (81.3558, 63.5576) -> (79.6792, 50.3463)
  curve K47 (81.6386, 70.4415) -> (81.3558, 63.5576)
  curve K48 (82.4897, 96.2198) -> (81.6386, 70.4415)
  curve K49 (82.9814, 112.3523) -> (82.4897, 96.2198)
  curve K50 (82.9821, 124.1958) -> (82.9814, 112.3523)
  curve K51 (-40.1501, 7.301) -> (-82.9821, 124.1958)
  curve K52 (-82.9813, 110.5256) -> (-82.9821, 124.1958)
  curve K53 (-82.2545, 88.8594) -> (-82.9813, 110.5256)
  curve K54 (-81.6277, 70.519) -> (-82.2545, 88.8594)
  curve K55 (-81.3572, 64.3441) -> (-81.6277, 70.519)
  curve K56 (-79.4149, 46.8924) -> (-81.3572, 64.3441)
  curve K57 (-76.5204, 38.9768) -> (-79.4149, 46.8924)
  curve K58 (-73.5142, 32.2947) -> (-76.5204, 38.9768)
  curve K59 (-72.5556, 30.3818) -> (-73.5142, 32.2947)
  curve K60 (-69.7914, 25.3691) -> (-72.5556, 30.3818)
  curve K61 (-68.3824, 23.4028) -> (-69.7914, 25.3691)
  curve K62 (-64.5419, 19.5456) -> (-68.3824, 23.4028)
  curve K63 (-62.3002, 17.7646) -> (-64.5419, 19.5456)
  curve K64 (-53.6583, 11.1976) -> (-62.3002, 17.7646)
  curve K65 (-49.6968, 10.1396) -> (-53.6583, 11.1976)
  curve K66 (-43.4141, 8.1331) -> (-49.6968, 10.1396)
  curve K67 (-41.9704, 7.6516) -> (-43.4141, 8.1331)
  curve K68 (-40.1963, 7.3098) -> (-41.9704, 7.6516)
  curve K69 (-40.1732, 7.3054) -> (-40.1963, 7.3098)
  curve K70 (-40.1501, 7.301) -> (-40.1732, 7.3054)
  line L5 (-82.9821, 124.1958) -> (-82.9821, 124.2212)
  line L6 (82.9821, 124.2212) -> (82.9821, 124.1958)
  line L7 (0, 317.5) -> (-50.8, 317.5)
  line L8 (7.2015, 3.048) -> (0, 3.048)
  line L9 (0, 3.048) -> (-7.2015, 3.048)
  arc A1 centre (0, 188.595) radius 185.6867 clockwise from (-7.2015, 3.048) to (-40.1502, 7.301)
  arc A2 centre (0, 188.595) radius 185.6867 clockwise from (40.151, 7.3012) to (7.2015, 3.048)
  point P38 (-40.1502, 7.301)
  point P43 (40.1509, 7.3012)
  point P62 (-40.1501, 7.301)
  point P81 (40.151, 7.3012)
  point P84 (0, 3.048)
  vertical L1
  horizontal L4
  coincident P38 K51
  symmetric L1 A1 A2
  coincident A2 P43
  coincident A1 P62
  coincident K31 P81
  perpendicular L2 L7
  horizontal L8
  coincident L1 P84
  horizontal L9
revolve "Revolve1" sketch "Sketch1" AlongAngle 360
shell "Shell1" innerThickness 3.81
fillet "Fillet1" radius 6.35 bodies "Balon v3"
offset_faces "OffsetFaces1" distance -50.8
move "Move1"
move "Move2"
component_from_bodies "Body->Comp1"
component_from_bodies "Body->Comp2"
sketch "Sketch2" plane through (0, 0, 0) normal (0, 1, 0) x axis (1, 0, 0)
  line L1 (-85.5221, 124.2212) -> (-85.5221, 124.1961)
  curve K1 (-58.9057, 236.4383) -> (-50.8, 241.7989)
  curve K2 (-50.8, 241.554) -> (-50.8, 241.7989)
  curve K3 (-50.904, 240.933) -> (-50.8, 241.554)
  curve K4 (-51.2936, 240.2837) -> (-50.904, 240.933)
  curve K5 (-51.734, 239.7561) -> (-51.2936, 240.2837)
  curve K6 (-53.328, 238.5038) -> (-51.734, 239.7561)
  curve K7 (-54.0892, 238.1997) -> (-53.328, 238.5038)
  curve K8 (-58.9057, 236.4383) -> (-54.0892, 238.1997)
  curve K9 (-89.3309, 124.2212) -> (-58.9057, 236.4383)
  curve K10 (-62.6336, 234.9735) -> (-58.9057, 236.4383)
  curve K11 (-65.581, 233.1032) -> (-62.6336, 234.9735)
  curve K12 (-73.0224, 227.0019) -> (-65.581, 233.1032)
  curve K13 (-74.8981, 224.836) -> (-73.0224, 227.0019)
  curve K14 (-78.1104, 219.6097) -> (-74.8981, 224.836)
  curve K15 (-80.2663, 215.561) -> (-78.1104, 219.6097)
  curve K16 (-84.0943, 205.8277) -> (-80.2663, 215.561)
  curve K17 (-85.4655, 200.1154) -> (-84.0943, 205.8277)
  curve K18 (-87.4092, 188.5789) -> (-85.4655, 200.1154)
  curve K19 (-87.7349, 182.3889) -> (-87.4092, 188.5789)
  curve K20 (-88.4233, 165.9645) -> (-87.7349, 182.3889)
  curve K21 (-89.328, 138.6964) -> (-88.4233, 165.9645)
  curve K22 (-89.3309, 124.2212) -> (-89.328, 138.6964)
  line L2 (-89.3309, 124.1958) -> (-89.3309, 124.2212)
  curve K23 (-46.5001, 7.301) -> (-89.3309, 124.1958)
  curve K24 (-89.3314, 112.4293) -> (-89.3309, 124.1958)
  curve K25 (-88.8181, 95.3068) -> (-89.3314, 112.4293)
  curve K26 (-88.346, 81.2892) -> (-88.8181, 95.3068)
  curve K27 (-88.0298, 70.4902) -> (-88.346, 81.2892)
  curve K28 (-87.1514, 58.328) -> (-88.0298, 70.4902)
  curve K29 (-86.3326, 50.6119) -> (-87.1514, 58.328)
  curve K30 (-81.0932, 33.6688) -> (-86.3326, 50.6119)
  curve K31 (-77.3163, 27.4309) -> (-81.0932, 33.6688)
  curve K32 (-74.8955, 23.6666) -> (-77.3163, 27.4309)
  curve K33 (-73.5108, 22.0741) -> (-74.8955, 23.6666)
  curve K34 (-70.2346, 19.0457) -> (-73.5108, 22.0741)
  curve K35 (-64.8094, 14.3548) -> (-70.2346, 19.0457)
  curve K36 (-56.6696, 10.3041) -> (-64.8094, 14.3548)
  curve K37 (-54.0053, 9.483) -> (-56.6696, 10.3041)
  curve K38 (-49.1487, 7.9411) -> (-54.0053, 9.483)
  curve K39 (-48.3482, 7.6526) -> (-49.1487, 7.9411)
  curve K40 (-46.5001, 7.301) -> (-48.3482, 7.6526)
  line L3 (0, 266.7) -> (0, 0)
  line L4 (0, 3.048) -> (-7.7894, 3.048)
  line L5 (-50.8, 266.7) -> (-50.8, 241.7989)
  line L6 (0, 266.7) -> (-50.8, 266.7)
  arc A1 centre (-6.9779, 188.7329) radius 185.6867 clockwise from (-7.7894, 3.048) to (-46.5001, 7.301)
  point P1 (0, 0)
  point P44 (0, 0)
  point P46 (0, 3.048)
  point P5 (-50.8, 241.554)
  point P49 (0, 266.7)
  coincident P1 P44
  coincident L3 P46
  coincident P5 L5
  coincident L3 P49
revolve "Revolve2" sketch "Sketch2" AlongAngle 360 bodies "Balon v3"
shell "Shell2" innerThickness 3.81
component_from_bodies "Body->Comp3"
remove_instance "RemoveInstance1"
remove_instance "RemoveInstance2"
sketch "Sketch1" plane through (0, 0, 0) normal (0, 1, 0) x axis (1, 0, 0)
  line L1 (-6.35, 3.048) -> (-14.1394, 3.048)
  curve K1 (-52.8501, 7.301) -> (-95.6809, 124.1958)
  curve K2 (-95.6814, 112.4293) -> (-95.6809, 124.1958)
  curve K3 (-95.1681, 95.3068) -> (-95.6814, 112.4293)
  curve K4 (-94.696, 81.2892) -> (-95.1681, 95.3068)
  curve K5 (-94.3798, 70.4902) -> (-94.696, 81.2892)
  curve K6 (-93.5014, 58.328) -> (-94.3798, 70.4902)
  curve K7 (-92.6826, 50.6119) -> (-93.5014, 58.328)
  curve K8 (-87.4432, 33.6688) -> (-92.6826, 50.6119)
  curve K9 (-83.6663, 27.4309) -> (-87.4432, 33.6688)
  curve K10 (-81.2455, 23.6666) -> (-83.6663, 27.4309)
  curve K11 (-79.8608, 22.0741) -> (-81.2455, 23.6666)
  curve K12 (-76.5846, 19.0457) -> (-79.8608, 22.0741)
  curve K13 (-71.12, 13.97) -> (-76.5846, 19.0457)
  curve K14 (-62.23, 10.16) -> (-71.12, 13.97)
  curve K15 (-60.3553, 9.483) -> (-62.23, 10.16)
  curve K16 (-55.4987, 7.9411) -> (-60.3553, 9.483)
  curve K17 (-54.6982, 7.6526) -> (-55.4987, 7.9411)
  curve K18 (-52.8501, 7.301) -> (-54.6982, 7.6526)
  line L2 (-95.6809, 124.1958) -> (-95.6809, 124.2212)
  line L3 (0, 266.7) -> (0, 0)
  line L4 (0, 3.048) -> (-6.35, 3.048)
  line L5 (-95.6809, 124.2466) -> (-95.6809, 124.2212)
  line L6 (-50.8, 266.7) -> (-50.8, 241.7989)
  line L7 (0, 266.7) -> (-50.8, 266.7)
  curve K19 (-71.6837, 232.5587) -> (-50.8, 241.7989)
  curve K20 (-50.8, 237.8015) -> (-50.8, 241.7989)
  curve K21 (-53.6019, 236.5654) -> (-50.8, 237.8015)
  curve K22 (-59.7861, 236.0598) -> (-53.6019, 236.5654)
  curve K23 (-64.4375, 235.2772) -> (-59.7861, 236.0598)
  curve K24 (-69.8917, 233.4707) -> (-64.4375, 235.2772)
  curve K25 (-71.6837, 232.5587) -> (-69.8917, 233.4707)
  curve K26 (-71.6837, 232.5587) -> (-95.6809, 124.2466)
  curve K27 (-95.6814, 136.0132) -> (-95.6809, 124.2466)
  curve K28 (-95.1681, 153.1357) -> (-95.6814, 136.0132)
  curve K29 (-94.696, 167.1533) -> (-95.1681, 153.1357)
  curve K30 (-94.3798, 177.9523) -> (-94.696, 167.1533)
  curve K31 (-93.5014, 190.1145) -> (-94.3798, 177.9523)
  curve K32 (-92.6826, 197.8306) -> (-93.5014, 190.1145)
  curve K33 (-87.4432, 214.7737) -> (-92.6826, 197.8306)
  curve K34 (-83.6663, 221.0115) -> (-87.4432, 214.7737)
  curve K35 (-81.2455, 224.7759) -> (-83.6663, 221.0115)
  curve K36 (-79.8608, 226.3684) -> (-81.2455, 224.7759)
  curve K37 (-77.083, 228.9361) -> (-79.8608, 226.3684)
  curve K38 (-75.5537, 230.2778) -> (-77.083, 228.9361)
  curve K39 (-71.6837, 232.5587) -> (-75.5537, 230.2778)
  curve K40 (-50.8, 244.8458) -> (-50.8, 244.8469)
  curve K41 (-50.8, 244.8465) -> (-50.8, 244.8469)
  curve K42 (-50.8, 244.8462) -> (-50.8, 244.8465)
  curve K43 (-50.8, 244.8458) -> (-50.8, 244.8462)
  arc A1 centre (-13.3279, 188.7329) radius 185.6867 clockwise from (-14.1394, 3.048) to (-52.8501, 7.301)
  point P26 (0, 3.048)
  point P33 (-50.8, 237.8015)
  point P35 (-50.8, 237.8015)
  point P40 (-71.6837, 232.5587)
  point P53 (-50.8, 244.8458)
  coincident L3 P26
  perpendicular L3 L4
  coincident P33 P35
  coincident K19 P40
  coincident L6 P53
sketch "Sketch2" plane through (0, 0, 0) normal (0, 1, 0) x axis (1, 0, 0)
  line L1 (-95.6809, 124.1958) -> (-95.6809, 124.2212)
  line L2 (0, 266.7) -> (-50.8, 266.7)
  curve K1 (-58.9317, 239.3909) -> (-50.8, 244.8469)
  curve K2 (-50.8, 244.602) -> (-50.8, 244.8469)
  curve K3 (-50.904, 243.981) -> (-50.8, 244.602)
  curve K4 (-51.2936, 243.3317) -> (-50.904, 243.981)
  curve K5 (-51.734, 242.8041) -> (-51.2936, 243.3317)
  curve K6 (-53.328, 241.5518) -> (-51.734, 242.8041)
  curve K7 (-54.0892, 241.2477) -> (-53.328, 241.5518)
  curve K8 (-58.9317, 239.3909) -> (-54.0892, 241.2477)
  line L3 (-50.8, 266.7) -> (-50.8, 244.8458)
  curve K9 (-52.8501, 7.301) -> (-95.6809, 124.1958)
  curve K10 (-95.6814, 112.4293) -> (-95.6809, 124.1958)
  curve K11 (-95.1681, 95.3068) -> (-95.6814, 112.4293)
  curve K12 (-94.696, 81.2892) -> (-95.1681, 95.3068)
  curve K13 (-94.3798, 70.4902) -> (-94.696, 81.2892)
  curve K14 (-93.5014, 58.328) -> (-94.3798, 70.4902)
  curve K15 (-92.6826, 50.6119) -> (-93.5014, 58.328)
  curve K16 (-87.4432, 33.6688) -> (-92.6826, 50.6119)
  curve K17 (-83.6663, 27.4309) -> (-87.4432, 33.6688)
  curve K18 (-81.2455, 23.6666) -> (-83.6663, 27.4309)
  curve K19 (-79.8608, 22.0741) -> (-81.2455, 23.6666)
  curve K20 (-76.5846, 19.0457) -> (-79.8608, 22.0741)
  curve K21 (-73.7599, 16.6033) -> (-76.5846, 19.0457)
  curve K22 (-65.532, 11.7145) -> (-73.7599, 16.6033)
  curve K23 (-60.3553, 9.483) -> (-65.532, 11.7145)
  curve K24 (-55.4987, 7.9411) -> (-60.3553, 9.483)
  curve K25 (-54.6982, 7.6526) -> (-55.4987, 7.9411)
  curve K26 (-52.8501, 7.301) -> (-54.6982, 7.6526)
  line L4 (-95.6809, 124.2466) -> (-95.6809, 124.2212)
  line L5 (0, 3.048) -> (-6.35, 3.048)
  line L6 (-6.35, 3.048) -> (-14.1394, 3.048)
  curve K27 (-58.9317, 239.3909) -> (-95.6809, 124.2466)
  curve K28 (-95.6814, 136.0132) -> (-95.6809, 124.2466)
  curve K29 (-95.1681, 153.1357) -> (-95.6814, 136.0132)
  curve K30 (-94.696, 167.1533) -> (-95.1681, 153.1357)
  curve K31 (-94.3798, 177.9523) -> (-94.696, 167.1533)
  curve K32 (-93.5014, 190.1145) -> (-94.3798, 177.9523)
  curve K33 (-92.6826, 197.8306) -> (-93.5014, 190.1145)
  curve K34 (-87.4432, 214.7737) -> (-92.6826, 197.8306)
  curve K35 (-83.6663, 221.0115) -> (-87.4432, 214.7737)
  curve K36 (-81.2455, 224.7759) -> (-83.6663, 221.0115)
  curve K37 (-79.8608, 226.3684) -> (-81.2455, 224.7759)
  curve K38 (-76.5846, 229.3968) -> (-79.8608, 226.3684)
  curve K39 (-73.7599, 231.8391) -> (-76.5846, 229.3968)
  curve K40 (-65.833, 236.5491) -> (-73.7599, 231.8391)
  curve K41 (-61.4585, 238.4785) -> (-65.833, 236.5491)
  curve K42 (-58.9317, 239.3909) -> (-61.4585, 238.4785)
  line L7 (0, 3.048) -> (0, 266.7)
  arc A1 centre (-13.3279, 188.7329) radius 185.6867 clockwise from (-14.1394, 3.048) to (-52.8501, 7.301)
  point P52 (-50.8, 244.8458)
  coincident K1 P52
  perpendicular L5 L7
revolve "Revolve1" sketch "Sketch1" AlongAngle 360 bodies "Balon v3.3"
shell "Shell1" innerThickness 3.81
revolve "Revolve2" sketch "Sketch2" AlongAngle 360 bodies "Balon v3.2"
shell "Shell2" innerThickness 3.81
component_from_bodies "Body->Comp1"
component_from_bodies "Body->Comp2"
position "Position1"
remove_instance "RemoveInstance1" bodies "Balon v3"
remove_instance "RemoveInstance2"
move "Move1"
position "Position2" bodies "Balon v3"
sketch "Sketch3" plane through (0, 0, 0) normal (0, 1, 0) x axis (1, 0, 0)
  line L1 (0, 50.8) -> (0, -304.8)
  line L2 (127, 50.8) -> (127, -304.8)
  line L3 (-127, 50.8) -> (-127, -304.8)
  line L4 (139.7, 25.4) -> (-139.7, 25.4)
  line L5 (139.7, -292.1) -> (-139.7, -292.1)
  line L6 (95.25, 50.8) -> (95.25, -304.8)
  vertical L1
  dimension "d6" = 127
  dimension "d12" = -127
  dimension "d17" distance L4 L5 = 317.5
  dimension "d18" = 95.25
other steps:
base_feature "Base Feature1" bodies "Balon v3.3"
base_feature "Base Feature1" bodies "Balon v3.2"
base_feature "Base Feature1" bodies "Balon"
base_feature "Base Feature1" bodies "Balon v3"
base_feature "Base Feature1" bodies "Balon v2"
create_component "CreateComponent1"
remove_body "RemoveBody1"
create_component "CreateComponent2"
remove_body "RemoveBody2"
create_component "CreateComponent3"
remove_body "RemoveBody3" bodies "Balon v3"
create_component "CreateComponent1"
create_component "CreateComponent2"
remove_body "RemoveBody1" bodies "Balon v3"
create_component "CreateComponent3"
remove_body "RemoveBody2" bodies "Balon v3"
named bodies: "Balon", "Balon v2", "Balon v3", "Balon v3.3", "Balon v3.2"

design "T8 LED 11" references "T9 - Bulb"
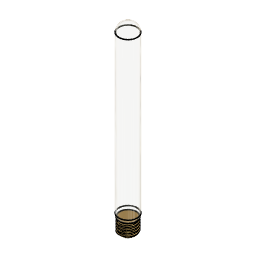
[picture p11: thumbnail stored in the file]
sketch "Sketch1" plane through (0, 0, 0) normal (0, 0, 1) x axis (1, 0, 0)
  circle C1 centre (0, 0) radius 14.986
  point P1 (0, 0)
  point P2 (0, 0)
  coincident P1 P2
  dimension "d1" diameter C1 = 29.972
sketch "Sketch2" plane through (0, 0, 0) normal (0, 1, 0) x axis (1, 0, 0)
  line L1 (0, -273.05) -> (0, 2.54)
  line L2 (15.24, -2.54) -> (15.24, -257.81)
  line L3 (-15.24, -257.81) -> (-15.24, -2.54)
  line L4 (0, 12.7) -> (0, -273.05)
  line L5 (-15.24, 2.54) -> (15.24, 2.54)
  arc A1 centre (0, -2.54) radius 15.24 clockwise from (-15.24, -2.54) to (15.24, -2.54)
  arc A2 centre (0, -257.81) radius 15.24 clockwise from (15.24, -257.81) to (-15.24, -257.81)
  point P2 (0, -273.05)
  point P9 (0, 12.7)
  point P12 (0, 2.54)
  point P1 (0, 0)
  vertical L1
  tangent L2 A1
  tangent A1 L3
  parallel L2 L3
  tangent L3 A2
  tangent L2 A2
  midpoint P2 A2
  midpoint A1 P9
  parallel L1 L4
  horizontal L5
  coincident L5 P12
  dimension "d2" distance P1 P2 = 273.05
revolve "Revolve1" sketch "Sketch2" AlongAngle 360
shell "Shell1" innerThickness 0.9906
external_derived "ExternalDerived1" bodies "E26 Base"
align "Align1"
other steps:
